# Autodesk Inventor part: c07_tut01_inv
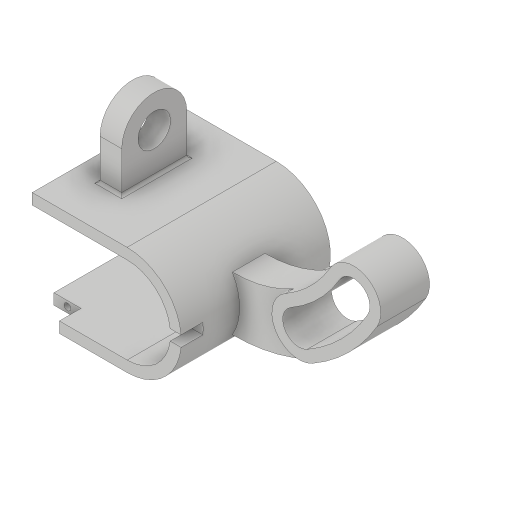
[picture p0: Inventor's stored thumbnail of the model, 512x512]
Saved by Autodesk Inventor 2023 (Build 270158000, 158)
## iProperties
Created: 2017-04
Part Number: c07_tut01_inv
Material: Generic
Document SubType Name: Modeling
Designer: CADCIM 00
Density: 1 g/cm^3
Appearance: Default
Author: CADCIM 00
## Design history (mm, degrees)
sketch "Sketch1"
  geometry: L1 (0, 16)-(35, 16); L2 (35, 16)-(35, 20); L3 (35, 20)-(0, 20); L4 (0, -20)-(35, -20); L5 (35, -20)-(35, -16); L6 (35, -16)-(0, -16); A1 r 16 centre (0, 0) between (0, 16) and (0, -16); A2 r 20 centre (0, 0) between (0, 20) and (0, -20); 1 further point
  constraints: 12 end point, 4 point on circle, 4 tangent, 3 perpendicular, 2 centre point, 2 point on line, 1 coincident, 1 concentric, 1 horizontal, 1 parallel
  dimensions: "d1" = 20 radius of A2; "d3" = 35 distance from line of point (0, 0) L5; "d37" = 16 radius of A1
extrude "Extrusion1" new body sketch "Sketch1" stored distance "d4" = 55; taper "d5" = 0 deg
sketch "Sketch2"
  geometry: A1 r 45 centre (-17.5, 55) between (-56.409, 32.393) and (-17.32, 10); A2 r 65 centre (-17.5, 55) between (-73.702, 22.345) and (-17.321, -10); A3 r 10 centre (-65.055, 27.369) between (-56.409, 32.393) and (-73.702, 22.345); A4 r 20 centre (0, 0) between (0, 20) and (0, -20) reference; A5 r 20 centre (0, 0) between (-17.32, 10) and (-17.321, -10); 1 further point
  constraints: 10 point on circle, 4 centre point, 2 tangent, 1 coincident
  dimensions: "d6" = 45 radius of A1; "d7" = 65 radius of A2; "d8" = 17.5 horizontal distance of point (0, 0) A1.centre; "d9" = 55 vertical distance of point (0, 0) A1.centre; "d10" = 60 deg dimension on A1.centre A3.centre A2.end
extrude "Extrusion2" join sketch "Sketch2" stored distance "d11" = 12; taper "d12" = 0 deg
sketch "Sketch3"
  geometry: A1 r 55 centre (-17.5, 55) between (-65.055, 27.369) and (-44.868, 7.293); A2 r 65 centre (-17.5, 55) between (-73.702, 22.345) and (-49.845, -1.381); A3 r 45 centre (-17.5, 55) between (-56.409, 32.393) and (-39.892, 15.967); A4 r 10 centre (-65.055, 27.369) between (-56.409, 32.393) and (-73.702, 22.345); A5 r 10 centre (-44.868, 7.293) between (-49.845, -1.381) and (-39.892, 15.967); A6 r 45 centre (-17.5, 55) between (-56.409, 32.393) and (-17.32, 10) reference; A7 r 65 centre (-17.5, 55) between (-73.702, 22.345) and (-17.321, -10) reference; A8 r 10 centre (-65.055, 27.369) between (-56.409, 32.393) and (-73.702, 22.345) reference; 1 further point
  constraints: 10 point on circle, 7 tangent, 5 centre point, 1 concentric
  dimensions: "d13" = 30 deg dimension on A1.centre A1.end A1.start
extrude "Extrusion3" join sketch "Sketch3" stored distance "d14" = 18; taper "d15" = 0 deg
sketch "Sketch4"
  geometry: A1 r 55 centre (17.5, 55) between (44.868, 7.293) and (65.055, 27.369); A2 r 61 centre (17.5, 55) between (47.854, 2.088) and (70.243, 24.354); A3 r 49 centre (17.5, 55) between (41.883, 12.497) and (59.867, 30.383); A4 r 6 centre (44.868, 7.293) between (41.883, 12.497) and (47.854, 2.088); A5 r 6 centre (65.055, 27.369) between (70.243, 24.354) and (59.867, 30.383); A6 r 45 centre (17.5, 55) between (39.892, 15.967) and (56.409, 32.393) reference; A7 r 10 centre (65.055, 27.369) between (73.702, 22.345) and (56.409, 32.393) reference; A8 r 10 centre (44.868, 7.293) between (39.892, 15.967) and (49.845, -1.381) reference; 1 further point
  constraints: 10 point on circle, 5 centre point, 4 tangent, 3 concentric
  dimensions: "d16" = 6 radius of A5
extrude "Extrusion4" cut sketch "Sketch4" extent not by distance; stored distance "d17" = 18; taper "d18" = 0 deg
workplane "Work Plane1"
sketch "Sketch5"
  geometry: L1 (0, 39.5)-(15, 39.5); L2 (15, 15.5)-(0, 15.5); L3 (0, 55)-(0, 0) reference; L4 (0, 39.5)-(0, 15.5); L5 (-40, 0)-(0, 0) reference; C1 r 6 at (15, 27.5); A1 r 12 centre (15, 27.5) between (15, 15.5) and (15, 39.5); 1 further point
  constraints: 6 end point, 2 centre point, 2 point on circle, 2 point on line, 2 tangent, 1 coincident, 1 collinear, 1 horizontal, 1 parallel
  dimensions: "d20" = 12 radius of A1; "d21" = 12 diameter of C1; "d22" = 15 distance from line of L3 A1.centre; "d23" = 27.5 distance from line of L5 A1.centre
extrude "Extrusion5" join sketch "Sketch5" distance "d24" = 8; taper "d25" = 0 deg
fillet "Fillet1" dims "d26" = 1
sketch "Sketch6"
  geometry: L1 (-35, -16)-(-35, -20) reference; L2 (-35, -20)-(0, -20) reference; L3 (-35, -16)-(-25, -16); L4 (-25, -16)-(-25, -20); L5 (-25, -20)-(-35, -20); L6 (-35, -20)-(-35, -16); L7 (15.631, 2)-(21.208, 2); L8 (21.208, 2)-(21.208, -2); L9 (21.208, -2)-(15.631, -2); L10 (15.631, -2)-(15.631, 2); A1 r 20 centre (0, 0) between (0, -20) and (0, 20) reference; 1 further point
  constraints: 16 end point, 4 parallel, 2 horizontal, 1 perpendicular, 1 point on line
  dimensions: "d27" = 10 distance of L1.start L3.end; "d28" = 4 distance of L9.end L7.start; "d29" = 2 distance from line of L7 point (0, 0)
extrude "Extrusion6" cut sketch "Sketch6" distance "d30" = 8; taper "d31" = 0 deg
sketch "Sketch7"
  geometry: L1 (-35, -20)-(-35, -16) reference; L2 (-25, -20)-(-35, -20) reference; C1 r 1.25 at (-30, -18); 1 further point
  constraints: 1 centre point
  dimensions: "d32" = 5 distance from line of L1 C1.centre; "d33" = 2 distance from line of L2 C1.centre; "d34" = 2.5 diameter of C1
extrude "Extrusion7" cut sketch "Sketch7" distance "d35" = 4; taper "d36" = 0 deg
body "Solid1"
other parameters: "d19" = -17.5
